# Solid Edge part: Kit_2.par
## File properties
Dokumentum tartalom típus: 0
Last saved by: bmolnar
Revision: 77
Sűrűség: 0,000 kg/m^3
Pontosság: 0,990
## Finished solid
Body 1: solid body, 23 faces, 39 edges, 29 vertices.
  Faces by surface: plane 11, cylinder 8, cone 3, torus 1
  Edges by curve: circle 21, line 18
Bounding box of the edges (mm; curved faces can reach further): 35.700 x 35.450 x 3.850, from (-17.85, -16.85, 0.6) to (17.85, 18.6, 4.45).
Cylindrical faces by radius (mm): R1.25 x2, R2.25 x2, R11.5 x1, R15.9 x1, R16.85 x1, R17.85 x1
Conical faces (half-angle, radius in mm at the cone's reference point): 45 deg R11.25 x1, 45 deg R16.75 x2
Toroidal faces (ring radius, tube radius in mm): R11.9 r0.4 x1
Planar faces by outward normal: +z 2, -z 5, oblique 4
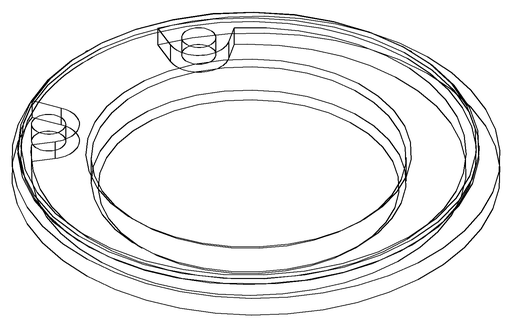
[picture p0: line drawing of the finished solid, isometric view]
